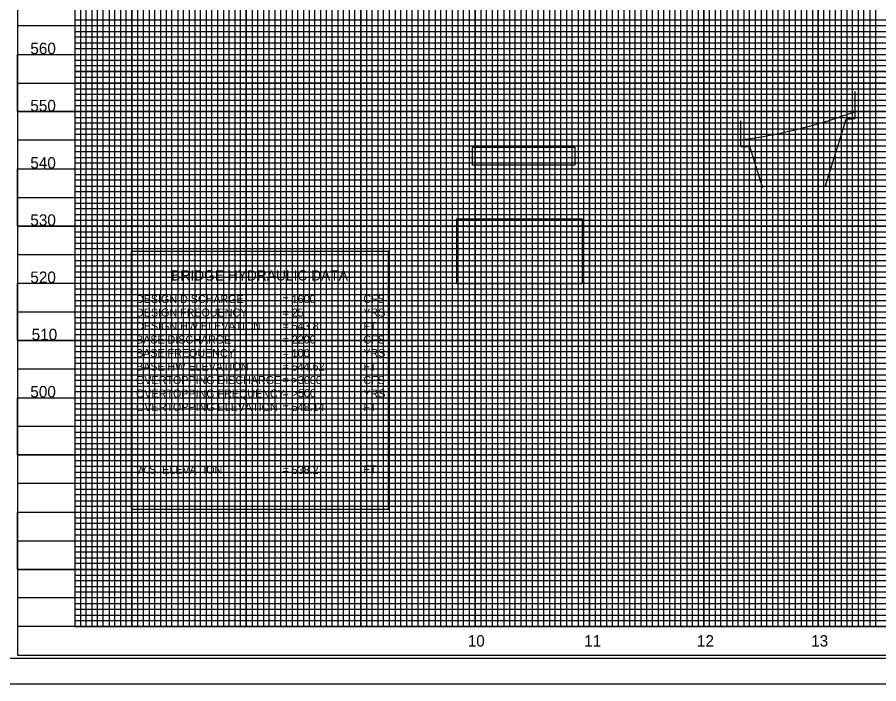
# Model space of a CAD drawing. Extents: x 1735444 to 1737729, y 696688 to 698970.
# Drawn here: x 1736212 to 1736965, y 697635 to 698218 of the extents above; entities that cross this region are included whole.
import ezdxf

# ---------------------------------------------------------------- set-up
doc = ezdxf.new("R2010")
doc.units = 0
for name, color, linetype in [('Default', 7, 'Continuous'), ('Exist Vertical Profile Horizontal Axis Label Major', 7, 'Continuous'), ('Exist Vertical Profile Vertical Axis Label', 7, 'Continuous'), ('Prop Grid Mask', 7, 'Continuous'), ('Scratch_Level_1', 7, 'Continuous'), ('Sheet Cutting Line CELL', 7, 'Continuous'), ('Sheet DOT Grid CELL', 7, 'Continuous'), ('Sheet Layout Profile Border', 7, 'Continuous'), ('Sheet Plot Border Inside CELL', 7, 'Continuous'), ('Sheet Plot Border Outside CELL', 7, 'Continuous'), ('Sheet Profile CELL', 7, 'Continuous'), ('Sheet Profile Grid Major CELL', 7, 'Continuous'), ('Sheet Profile Grid Middle CELL', 7, 'Continuous'), ('Sheet Profile Grid Minor CELL', 7, 'Continuous')]:
    doc.layers.add(name, color=color, linetype=linetype)

msp = doc.modelspace()

# ---------------------------------------------------------------- linework, layer by layer
at = {"layer": 'Prop Grid Mask'}
for points in [[(1736609.73, 698104.11), (1736699.36, 698104.11), (1736699.36, 698088.35), (1736609.73, 698088.35)], [(1736596.19, 698041.4), (1736705.72, 698041.4), (1736705.72, 697984.52), (1736596.19, 697984.52)], [(1736311.49, 697787.8), (1736536.49, 697787.8), (1736536.49, 698012.8), (1736311.49, 698012.8)]]:
    msp.add_lwpolyline(points, close=True, dxfattribs=at)
at = {"layer": 'Scratch_Level_1'}
for p, q in [((1736944.34, 698129.09), (1736944.34, 698152.86)), ((1736918.42, 698070.15), (1736936.55, 698128.66)), ((1736844.34, 698104.67), (1736844.34, 698127.02)), ((1736863.62, 698068.19), (1736852.27, 698104.8))]:
    msp.add_line(p, q, dxfattribs=at)
for points, degree in [([(1736844.34, 698110.47), (1736845.77, 698110.65), (1736847.2, 698110.84), (1736855.2, 698111.95), (1736861.76, 698113.02), (1736874.82, 698115.44), (1736881.31, 698116.8), (1736894.23, 698119.79), (1736900.66, 698121.43), (1736913.42, 698124.97), (1736919.76, 698126.88), (1736932.19, 698130.89), (1736938.29, 698133), (1736944.34, 698135.21)], 3), ([(1736936.55, 698128.66), (1736939.15, 698128.8), (1736941.74, 698128.94), (1736944.34, 698129.09)], 2), ([(1736844.34, 698104.67), (1736846.98, 698104.71), (1736849.63, 698104.75), (1736852.27, 698104.8)], 2)]:
    msp.add_open_spline(points, degree=degree, dxfattribs=at)
at = {"layer": 'Sheet Cutting Line CELL'}
msp.add_line((1736045.07, 697635.13), (1737729.07, 697635.13), dxfattribs=at)
at = {"layer": 'Sheet DOT Grid CELL'}
for p, q in [((1736262.07, 698710.13), (1736262.07, 697685.13)), ((1736312.07, 698710.13), (1736312.07, 697685.13)), ((1736362.07, 698710.13), (1736362.07, 697685.13)), ((1736412.07, 698710.13), (1736412.07, 697685.13)), ((1736462.07, 698710.13), (1736462.07, 697685.13)), ((1736512.07, 698710.13), (1736512.07, 697685.13)), ((1736562.07, 698710.13), (1736562.07, 697685.13)), ((1736612.07, 698710.13), (1736612.07, 697685.13)), ((1736662.07, 698710.13), (1736662.07, 697685.13)), ((1736712.07, 698710.13), (1736712.07, 697685.13)), ((1736762.07, 698710.13), (1736762.07, 697685.13)), ((1736812.07, 698710.13), (1736812.07, 697685.13)), ((1736862.07, 698710.13), (1736862.07, 697685.13)), ((1736912.07, 698710.13), (1736912.07, 697685.13)), ((1736962.07, 698710.13), (1736962.07, 697685.13)), ((1736212.07, 698185.13), (1737712.07, 698185.13)), ((1736212.07, 698135.13), (1737712.07, 698135.13)), ((1736212.07, 698085.13), (1737712.07, 698085.13)), ((1736212.07, 698035.13), (1737712.07, 698035.13)), ((1736212.07, 697985.13), (1737712.07, 697985.13)), ((1736212.07, 697935.13), (1737712.07, 697935.13)), ((1736212.07, 697885.13), (1737274.3, 697885.13)), ((1736212.07, 697835.13), (1737274.9, 697835.13)), ((1736212.07, 697785.13), (1737274.3, 697785.13)), ((1736212.07, 697735.13), (1737274.3, 697735.13))]:
    msp.add_line(p, q, dxfattribs=at)
at = {"layer": 'Sheet Layout Profile Border'}
msp.add_lwpolyline([(1737512.02, 698661.7), (1737512.02, 698710.13), (1736262.07, 698710.13), (1736262.07, 697685.13), (1737662.07, 697685.13), (1737662.07, 698572.58), (1737512.02, 698572.58), (1737512.02, 698617.69)], dxfattribs=at)
at = {"layer": 'Sheet Plot Border Inside CELL'}
msp.add_lwpolyline([(1737724.57, 698712.68), (1736058.07, 698712.68), (1736058.07, 697657.58), (1737724.57, 697657.58)], close=True, dxfattribs=at)
at = {"layer": 'Sheet Plot Border Outside CELL'}
msp.add_lwpolyline([(1737729.07, 698735.13), (1736045.07, 698735.13), (1736045.07, 697635.13), (1737729.07, 697635.13)], close=True, dxfattribs=at)
at = {"layer": 'Sheet Profile CELL'}
for p, q in [((1737712.07, 697685.13), (1736212.07, 697685.13)), ((1736212.07, 697660.13), (1736212.07, 697660.13)), ((1736212.07, 697660.13), (1736212.07, 697660.13)), ((1736212.07, 697660.13), (1736212.07, 697660.13)), ((1736212.07, 697660.13), (1736212.07, 697660.13)), ((1736212.07, 697660.13), (1736212.07, 697660.13)), ((1736212.07, 697660.13), (1736212.07, 697660.13))]:
    msp.add_line(p, q, dxfattribs=at)
msp.add_lwpolyline([(1737712.07, 698710.13), (1736212.07, 698710.13), (1736212.07, 697660.13), (1737712.07, 697660.13)], close=True, dxfattribs=at)
msp.add_lwpolyline([(1736249.57, 697660.13), (1736249.57, 697660.13)], dxfattribs=at)
at = {"layer": 'Sheet Profile Grid Major CELL'}
for points in [[(1736262.07, 698710.13), (1736262.07, 697685.13), (1736312.07, 697685.13), (1736312.07, 698710.13)], [(1736362.07, 698710.13), (1736362.07, 697685.13), (1736412.07, 697685.13), (1736412.07, 698710.13)], [(1736462.07, 698710.13), (1736462.07, 697685.13), (1736512.07, 697685.13), (1736512.07, 698710.13)], [(1736562.07, 698710.13), (1736562.07, 697685.13), (1736612.07, 697685.13), (1736612.07, 698710.13)], [(1736662.07, 698710.13), (1736662.07, 697685.13), (1736712.07, 697685.13), (1736712.07, 698710.13)], [(1736762.07, 698710.13), (1736762.07, 697685.13), (1736812.07, 697685.13), (1736812.07, 698710.13)], [(1736862.07, 698710.13), (1736862.07, 697685.13), (1736912.07, 697685.13), (1736912.07, 698710.13)], [(1736962.07, 698710.13), (1736962.07, 697685.13), (1737012.07, 697685.13)], [(1737712.07, 698135.13), (1736212.07, 698135.13), (1736212.07, 698185.13), (1737712.07, 698185.13)], [(1737712.07, 698035.13), (1736212.07, 698035.13), (1736212.07, 698085.13), (1737712.07, 698085.13)], [(1737712.07, 697935.13), (1736212.07, 697935.13), (1736212.07, 697985.13), (1737712.07, 697985.13)], [(1737712.07, 697835.13), (1736212.07, 697835.13), (1736212.07, 697885.13), (1737712.07, 697885.13)], [(1737712.07, 697735.13), (1736212.07, 697735.13), (1736212.07, 697785.13), (1737712.07, 697785.13)]]:
    msp.add_lwpolyline(points, dxfattribs=at)
at = {"layer": 'Sheet Profile Grid Middle CELL'}
for points in [[(1736287.07, 697685.13), (1736287.07, 698710.13)], [(1736337.07, 698710.13), (1736337.07, 697685.13), (1736387.07, 697685.13), (1736387.07, 698710.13)], [(1736437.07, 698710.13), (1736437.07, 697685.13), (1736487.07, 697685.13), (1736487.07, 698710.13)], [(1736537.07, 698710.13), (1736537.07, 697685.13), (1736587.07, 697685.13), (1736587.07, 698710.13)], [(1736637.07, 698710.13), (1736637.07, 697685.13), (1736687.07, 697685.13), (1736687.07, 698710.13)], [(1736737.07, 698710.13), (1736737.07, 697685.13), (1736787.07, 697685.13), (1736787.07, 698710.13)], [(1736837.07, 698710.13), (1736837.07, 697685.13), (1736887.07, 697685.13), (1736887.07, 698710.13)], [(1736937.07, 698710.13), (1736937.07, 697685.13), (1736987.07, 697685.13)], [(1737712.07, 698210.13), (1736212.07, 698210.13), (1736212.07, 698160.13), (1737712.07, 698160.13)], [(1737712.07, 698110.13), (1736212.07, 698110.13), (1736212.07, 698060.13), (1737712.07, 698060.13)], [(1737712.07, 698010.13), (1736212.07, 698010.13), (1736212.07, 697960.13), (1737712.07, 697960.13)], [(1737275.01, 697910.13), (1736212.07, 697910.13), (1736212.07, 697860.13), (1737274.3, 697860.13)], [(1737274.9, 697810.13), (1736212.07, 697810.13), (1736212.07, 697760.13), (1737274.01, 697760.13)], [(1737712.07, 697710.13), (1736212.07, 697710.13)]]:
    msp.add_lwpolyline(points, dxfattribs=at)
at = {"layer": 'Sheet Profile Grid Minor CELL'}
for points in [[(1736267.07, 698710.13), (1736267.07, 697685.13), (1736272.07, 697685.13), (1736272.07, 698710.13)], [(1736277.07, 698710.13), (1736277.07, 697685.13), (1736282.07, 697685.13), (1736282.07, 698710.13)], [(1736292.07, 698710.13), (1736292.07, 697685.13), (1736297.07, 697685.13), (1736297.07, 698710.13)], [(1736302.07, 698710.13), (1736302.07, 697685.13), (1736307.07, 697685.13), (1736307.07, 698710.13)], [(1736317.07, 698710.13), (1736317.07, 697685.13), (1736322.07, 697685.13), (1736322.07, 698710.13)], [(1736327.07, 698710.13), (1736327.07, 697685.13), (1736332.07, 697685.13), (1736332.07, 698710.13)], [(1736342.07, 698710.13), (1736342.07, 697685.13), (1736347.07, 697685.13), (1736347.07, 698710.13)], [(1736352.07, 698710.13), (1736352.07, 697685.13), (1736357.07, 697685.13), (1736357.07, 698710.13)], [(1736367.07, 698710.13), (1736367.07, 697685.13), (1736372.07, 697685.13), (1736372.07, 698710.13)], [(1736377.07, 698710.13), (1736377.07, 697685.13), (1736382.07, 697685.13), (1736382.07, 698710.13)], [(1736392.07, 698710.13), (1736392.07, 697685.13), (1736397.07, 697685.13), (1736397.07, 698710.13)], [(1736402.07, 698710.13), (1736402.07, 697685.13), (1736407.07, 697685.13), (1736407.07, 698710.13)], [(1736417.07, 698710.13), (1736417.07, 697685.13), (1736422.07, 697685.13), (1736422.07, 698710.13)], [(1736427.07, 697685.13), (1736432.07, 697685.13), (1736432.07, 698710.13)], [(1736427.07, 698710.13), (1736427.07, 697685.13)], [(1736442.07, 698710.13), (1736442.07, 697685.13), (1736447.07, 697685.13), (1736447.07, 698710.13)], [(1736452.07, 698710.13), (1736452.07, 697685.13), (1736457.07, 697685.13), (1736457.07, 698710.13)], [(1736467.07, 698710.13), (1736467.07, 697685.13), (1736472.07, 697685.13), (1736472.07, 698710.13)], [(1736477.07, 698710.13), (1736477.07, 697685.13), (1736482.07, 697685.13), (1736482.07, 698710.13)], [(1736492.07, 698710.13), (1736492.07, 697685.13), (1736497.07, 697685.13), (1736497.07, 698710.13)], [(1736502.07, 698710.13), (1736502.07, 697685.13), (1736507.07, 697685.13), (1736507.07, 698710.13)], [(1736517.07, 698710.13), (1736517.07, 697685.13), (1736522.07, 697685.13), (1736522.07, 698710.13)], [(1736527.07, 698710.13), (1736527.07, 697685.13), (1736532.07, 697685.13), (1736532.07, 698710.13)], [(1736542.07, 698710.13), (1736542.07, 697685.13), (1736547.07, 697685.13), (1736547.07, 698710.13)], [(1736552.07, 698710.13), (1736552.07, 697685.13), (1736557.07, 697685.13), (1736557.07, 698710.13)], [(1736567.07, 698710.13), (1736567.07, 697685.13), (1736572.07, 697685.13), (1736572.07, 698710.13)], [(1736577.07, 698710.13), (1736577.07, 697685.13), (1736582.07, 697685.13), (1736582.07, 698710.13)], [(1736592.07, 698710.13), (1736592.07, 697685.13), (1736607.07, 697685.13), (1736607.07, 698710.13)], [(1736597.07, 698710.13), (1736597.07, 697685.13), (1736602.07, 697685.13), (1736602.07, 698710.13)], [(1736597.07, 698709.53), (1736597.07, 697685.13), (1736602.07, 697685.13), (1736602.07, 698709.53)], [(1736617.07, 698710.13), (1736617.07, 697685.13), (1736622.07, 697685.13), (1736622.07, 698710.13)], [(1736627.07, 698710.13), (1736627.07, 697685.13), (1736632.07, 697685.13), (1736632.07, 698710.13)], [(1736642.07, 698710.13), (1736642.07, 697685.13), (1736647.07, 697685.13), (1736647.07, 698710.13)], [(1736652.07, 698710.13), (1736652.07, 697685.13), (1736657.07, 697685.13), (1736657.07, 698710.13)], [(1736667.07, 698710.13), (1736667.07, 697685.13), (1736672.07, 697685.13), (1736672.07, 698710.13)], [(1736677.07, 698710.13), (1736677.07, 697685.13), (1736682.07, 697685.13), (1736682.07, 698710.13)], [(1736692.07, 698710.13), (1736692.07, 697685.13), (1736697.07, 697685.13), (1736697.07, 698710.13)], [(1736702.07, 698710.13), (1736702.07, 697685.13), (1736707.07, 697685.13), (1736707.07, 698710.13)], [(1736717.07, 698710.13), (1736717.07, 697685.13), (1736722.07, 697685.13), (1736722.07, 698710.13)], [(1736727.07, 698710.13), (1736727.07, 697685.13), (1736732.07, 697685.13), (1736732.07, 698710.13)], [(1736742.07, 698710.13), (1736742.07, 697685.13)], [(1736747.07, 698710.13), (1736747.07, 697685.13), (1736752.07, 697685.13), (1736752.07, 698710.13), (1736757.07, 698710.13), (1736757.07, 697685.13), (1736767.07, 697685.13), (1736767.07, 698710.13), (1736772.07, 698710.13), (1736772.07, 697685.13), (1736777.07, 697685.13), (1736777.07, 698710.13), (1736782.07, 698710.13), (1736782.07, 697685.13)], [(1736792.07, 697685.13), (1736792.07, 698710.13)], [(1736797.07, 698710.13), (1736797.07, 697685.13), (1736802.07, 697685.13), (1736802.07, 698710.13)], [(1736807.07, 698710.13), (1736807.07, 697685.13), (1736817.07, 697685.13), (1736817.07, 698710.13)], [(1736822.07, 698710.13), (1736822.07, 697685.13), (1736822.07, 697685.13), (1736827.07, 697685.13), (1736827.07, 698710.13)], [(1736832.07, 698710.13), (1736832.07, 697685.13), (1736842.07, 697685.13), (1736842.07, 698710.13)], [(1736847.07, 698710.13), (1736847.07, 697685.13), (1736852.07, 697685.13), (1736852.07, 698710.13)], [(1736857.07, 698710.13), (1736857.07, 697685.13), (1736867.07, 697685.13), (1736867.07, 698710.13)], [(1736872.07, 698710.13), (1736872.07, 697685.13), (1736877.07, 697685.13), (1736877.07, 698710.13)], [(1736882.07, 698710.13), (1736882.07, 697685.13), (1736892.07, 697685.13), (1736892.07, 698710.13)], [(1736897.07, 698710.13), (1736897.07, 697685.13), (1736902.07, 697685.13), (1736902.07, 698710.13)], [(1736907.07, 698710.13), (1736907.07, 697685.13), (1736917.07, 697685.13), (1736917.07, 698710.13)], [(1736922.07, 698710.13), (1736922.07, 697685.13), (1736927.07, 697685.13), (1736927.07, 698710.13)], [(1736932.07, 698710.13), (1736932.07, 697685.13), (1736942.07, 697685.13), (1736942.07, 698710.13)], [(1736947.07, 698710.13), (1736947.07, 697685.13), (1736952.07, 697685.13), (1736952.07, 698710.13)], [(1736957.07, 698710.13), (1736957.07, 697685.13), (1736967.07, 697685.13)], [(1737262.07, 698215.13), (1736262.07, 698215.13), (1736262.07, 698205.13), (1737262.07, 698205.13)], [(1737262.07, 698200.13), (1736262.07, 698200.13), (1736262.07, 698195.13), (1737262.07, 698195.13)], [(1737262.07, 698190.13), (1736262.07, 698190.13)], [(1736262.07, 698180.13), (1737262.07, 698180.13)], [(1737262.07, 698175.13), (1736262.07, 698175.13), (1736262.07, 698170.13), (1737262.07, 698170.13)], [(1737262.07, 698170.13), (1736262.07, 698170.13), (1736262.07, 698165.13), (1737262.07, 698165.13)], [(1737662.07, 698160.13), (1736262.07, 698160.13), (1736262.07, 698155.13), (1737262.07, 698155.13)], [(1737262.07, 698150.13), (1736262.07, 698150.13), (1736262.07, 698145.13), (1737262.07, 698145.13)], [(1737262.07, 698140.13), (1736262.07, 698140.13), (1736262.07, 698130.13), (1737262.07, 698130.13)], [(1737262.07, 698125.13), (1736262.07, 698125.13), (1736262.07, 698120.13), (1737262.07, 698120.13)], [(1737262.07, 698115.13), (1736262.07, 698115.13), (1736262.07, 698105.13), (1737262.07, 698105.13)], [(1737262.07, 698100.13), (1736262.07, 698100.13), (1736262.07, 698095.13), (1737262.07, 698095.13)], [(1737262.07, 698090.13), (1736262.07, 698090.13), (1736262.07, 698080.13), (1737262.07, 698080.13)], [(1737262.07, 698075.13), (1736262.07, 698075.13), (1736262.07, 698070.13), (1737262.07, 698070.13)], [(1737262.07, 698065.13), (1736262.07, 698065.13), (1736262.07, 698055.13), (1737262.07, 698055.13)], [(1737262.07, 698050.13), (1736262.07, 698050.13), (1736262.07, 698045.13), (1737262.07, 698045.13)], [(1737262.07, 698040.13), (1736262.07, 698040.13), (1736262.07, 698030.13), (1737262.07, 698030.13)], [(1737262.07, 698025.13), (1736262.07, 698025.13), (1736262.07, 698020.13), (1737262.07, 698020.13)], [(1737262.07, 698015.13), (1736262.07, 698015.13), (1736262.07, 698005.13), (1737262.07, 698005.13)], [(1737262.07, 698000.13), (1736262.07, 698000.13), (1736262.07, 697995.13), (1737262.07, 697995.13)], [(1737262.07, 697990.13), (1736262.07, 697990.13), (1736262.07, 697980.13), (1737262.07, 697980.13)], [(1737262.07, 697975.13), (1736262.07, 697975.13), (1736262.07, 697970.13), (1737262.07, 697970.13)], [(1737262.07, 697965.13), (1736262.07, 697965.13), (1736262.07, 697955.13), (1737262.07, 697955.13)], [(1737262.07, 697950.13), (1736262.07, 697950.13), (1736262.07, 697945.13), (1737262.07, 697945.13)], [(1737262.07, 697940.13), (1736262.07, 697940.13), (1736262.07, 697930.13), (1737262.07, 697930.13)], [(1737262.07, 697925.13), (1736262.07, 697925.13), (1736262.07, 697920.13), (1737262.07, 697920.13)], [(1737262.07, 697915.13), (1736262.07, 697915.13), (1736262.07, 697905.13), (1737262.07, 697905.13)], [(1737262.07, 697900.13), (1736262.07, 697900.13), (1736262.07, 697895.13), (1737262.07, 697895.13)], [(1737262.07, 697890.13), (1736262.07, 697890.13)], [(1736262.07, 697880.13), (1737262.07, 697880.13)], [(1737262.07, 697875.13), (1736262.07, 697875.13), (1736262.07, 697870.13), (1737262.07, 697870.13)], [(1737262.07, 697865.13), (1736262.07, 697865.13)], [(1736262.07, 697855.13), (1737262.07, 697855.13)], [(1737262.07, 697850.13), (1736262.07, 697850.13), (1736262.07, 697845.13), (1737262.07, 697845.13)], [(1737262.07, 697840.13), (1736262.07, 697840.13), (1736262.07, 697830.13), (1737262.07, 697830.13)], [(1737262.07, 697825.13), (1736262.07, 697825.13), (1736262.07, 697820.13), (1737262.07, 697820.13)], [(1737262.07, 697815.13), (1736262.07, 697815.13), (1736262.07, 697805.13), (1737262.07, 697805.13)], [(1737262.07, 697800.13), (1736262.07, 697800.13), (1736262.07, 697795.13), (1737262.07, 697795.13)], [(1737262.07, 697790.13), (1736262.07, 697790.13), (1736262.07, 697780.13), (1737262.07, 697780.13)], [(1737262.07, 697775.13), (1736262.07, 697775.13), (1736262.07, 697770.13), (1737262.07, 697770.13)], [(1737262.07, 697765.13), (1736262.07, 697765.13), (1736262.07, 697755.13), (1737262.07, 697755.13)], [(1737262.07, 697750.13), (1736262.07, 697750.13), (1736262.07, 697745.13), (1737262.07, 697745.13)], [(1737262.07, 697740.13), (1736262.07, 697740.13), (1736262.07, 697730.13), (1737262.07, 697730.13)], [(1737262.07, 697725.13), (1736262.07, 697725.13), (1736262.07, 697720.13), (1737262.07, 697720.13)], [(1737262.07, 697715.13), (1736262.07, 697715.13), (1736262.07, 697705.13), (1737262.07, 697705.13)], [(1737262.07, 697700.13), (1736262.07, 697700.13), (1736262.07, 697695.13), (1737262.07, 697695.13)], [(1737262.07, 697690.13), (1736262.07, 697690.13)]]:
    msp.add_lwpolyline(points, dxfattribs=at)

# ---------------------------------------------------------------- texts
at = {"layer": 'Default'}
for s, height, p in [('BRIDGE HYDRAULIC DATA', 9, (1736346.39, 697987.55)), ('DESIGN DISCHARGE', 7, (1736315.69, 697967.85)), ('= 1600    ', 7, (1736443.76, 697967.85)), ('CFS', 7, (1736514.41, 697967.95)), ('DESIGN FREQUENCY', 7, (1736315.69, 697956.05)), ('= 25 ', 7, (1736443.76, 697956.05)), ('YRS', 7, (1736514.41, 697956.05)), ('DESIGN HW ELEVATION', 7, (1736315.69, 697944.25)), ('= 543.8   ', 7, (1736443.76, 697944.25)), ('FT', 7, (1736514.41, 697944.25)), ('BASE DISCHARGE', 7, (1736315.69, 697932.45)), ('= 2200    ', 7, (1736443.76, 697932.45)), ('CFS', 7, (1736514.41, 697932.45)), ('BASE FREQUENCY', 7, (1736315.69, 697920.65)), ('= 100', 7, (1736443.76, 697920.65)), ('YRS', 7, (1736514.41, 697920.65)), ('BASE HW ELEVATION', 7, (1736315.69, 697908.85)), ('= 544.62  ', 7, (1736443.76, 697908.85)), ('FT', 7, (1736514.41, 697908.85)), ('OVERTOPPING DISCHARGE', 7, (1736315.69, 697897.05)), ('= >3000   ', 7, (1736443.76, 697897.05)), ('CFS', 7, (1736514.41, 697897.05)), ('OVERTOPPING FREQUENCY', 7, (1736315.69, 697885.25)), ('= >500', 7, (1736443.76, 697885.54)), ('YRS', 7, (1736514.41, 697885.25)), ('OVERTOPPING ELEVATION', 7, (1736315.69, 697873.45)), ('= 548.14  ', 7, (1736443.76, 697873.45)), ('FT', 7, (1736514.41, 697873.45)), ('W.S. ELEVATION', 7, (1736315.69, 697818.75)), ('= 538.2   ', 7, (1736443.76, 697818.49)), ('FT', 7, (1736514.41, 697819.09))]:
    msp.add_text(s, height=height, dxfattribs=at).set_placement(p)
at = {"layer": 'Exist Vertical Profile Horizontal Axis Label Major'}
for s, p in [('10', (1736605.66, 697667.63)), ('11', (1736707.49, 697667.63)), ('12', (1736806.04, 697667.63)), ('13', (1736905.88, 697667.63))]:
    msp.add_text(s, height=10, dxfattribs=at).set_placement(p)
at = {"layer": 'Exist Vertical Profile Vertical Axis Label'}
for s, p in [('560', (1736223.25, 698185.38)), ('550', (1736223.25, 698135.38)), ('540', (1736223.25, 698085.38)), ('530', (1736223.25, 698035.38)), ('520', (1736223.25, 697985.38)), ('510', (1736224.44, 697935.38)), ('500', (1736223.25, 697885.38))]:
    msp.add_text(s, height=10, dxfattribs=at).set_placement(p)

doc.saveas('drawing.dxf')
